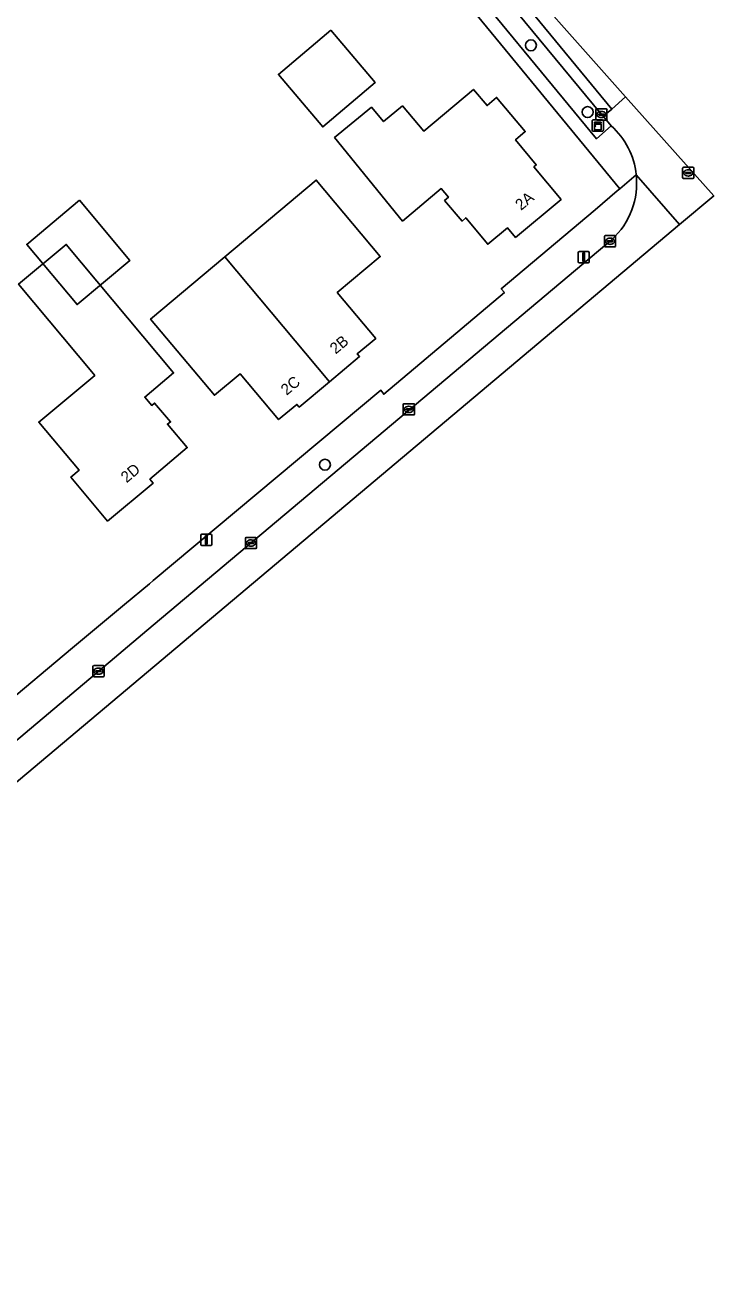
# Model space of a CAD drawing. Extents: x 156702 to 158052, y 387630 to 388992.
# Drawn here: x 157599.6 to 157661.3, y 387864.2 to 387977.5 of the extents above; entities that cross this region are included whole.
import ezdxf

# ---------------------------------------------------------------- set-up
doc = ezdxf.new("R2010")
doc.units = 0
for name, color, linetype in [('IMGEO_Boom', 7, 'Continuous'), ('IMGEO_Erf', 7, 'Continuous'), ('IMGEO_Groenvoorziening', 7, 'Continuous'), ('IMGEO_Kast', 7, 'Continuous'), ('IMGEO_Kolk', 7, 'Continuous'), ('IMGEO_Lichtmast', 7, 'Continuous'), ('IMGEO_Pand', 7, 'Continuous'), ('IMGEO_Pand_nummerreeks', 7, 'Continuous'), ('IMGEO_Pand_vergunning_verleend', 7, 'Continuous'), ('IMGEO_Rijbaan_lokaal_open', 7, 'Continuous'), ('IMGEO_Rioolput', 7, 'Continuous'), ('IMGEO_Voetpad_open', 7, 'Continuous')]:
    doc.layers.add(name, color=color, linetype=linetype)

msp = doc.modelspace()

# ---------------------------------------------------------------- linework, layer by layer
at = {"layer": 'IMGEO_Boom'}
for centre in [(157644.93, 387975.67), (157650.01, 387969.69), (157626.48, 387938.13)]:
    msp.add_circle(centre, 0.489, dxfattribs=at)
at = {"layer": 'IMGEO_Erf'}
for points in [[(157610.76, 387927.47), (157611.11, 387927.75), (157631.49, 387944.79), (157631.75, 387944.44), (157642.56, 387953.55), (157642.27, 387953.88), (157650.67, 387960.94), (157652.64, 387962.64), (157652.9, 387962.82), (157636.22, 387983.07), (157635.31, 387982.52)], [(157590.77, 387910.76), (157603.87, 387921.74), (157608.52, 387925.63), (157610.76, 387927.47)]]:
    msp.add_lwpolyline(points, dxfattribs=at)
for points in [[(157627.34, 387967.41), (157630.65, 387970.13), (157631.73, 387968.85), (157633.42, 387970.25), (157635.33, 387967.99), (157639.78, 387971.72), (157641, 387970.28), (157641.86, 387971.01), (157644.42, 387967.95), (157643.56, 387967.21), (157645.41, 387964.97), (157645.2, 387964.78), (157647.63, 387961.87), (157643.56, 387958.48), (157642.83, 387959.34), (157641.07, 387957.86), (157639.09, 387960.23), (157638.76, 387959.93), (157637.19, 387961.77), (157637.54, 387962.07), (157636.9, 387962.84), (157633.43, 387959.93)], [(157610.86, 387951.17), (157617.51, 387956.73), (157625.71, 387963.6), (157631.43, 387956.76), (157627.59, 387953.54), (157631.03, 387949.43), (157629.37, 387948.06), (157629.59, 387947.82), (157626.89, 387945.55), (157624.18, 387943.28), (157623.97, 387943.52), (157622.33, 387942.17), (157618.9, 387946.26), (157616.59, 387944.34)], [(157599.04, 387954.29), (157603.31, 387957.85), (157612.93, 387946.34), (157610.34, 387944.19), (157610.97, 387943.43), (157611.23, 387943.65), (157612.65, 387941.96), (157612.38, 387941.76), (157614.15, 387939.66), (157610.81, 387936.83), (157611.1, 387936.49), (157607.02, 387933.08), (157603.73, 387937.02), (157604.46, 387937.63), (157600.85, 387941.94), (157605.87, 387946.12), (157605.75, 387946.27)]]:
    msp.add_lwpolyline(points, close=True, dxfattribs=at)
at = {"layer": 'IMGEO_Groenvoorziening'}
msp.add_lwpolyline([(157636.52, 387983.99), (157636.86, 387984.23), (157650.8, 387967.3), (157652.11, 387968.45), (157651.4, 387969.32), (157651.24, 387969.48), (157639.51, 387983.68), (157638.8, 387984.55)], dxfattribs=at)
at = {"layer": 'IMGEO_Kast'}
for p, q in [((157650.42, 387968.06), (157650.42, 387968.9)), ((157650.42, 387968.9), (157650.42, 387968.06)), ((157650.49, 387968.99), (157651.33, 387968.99)), ((157651.33, 387968.99), (157650.49, 387968.99)), ((157651.42, 387968.91), (157651.42, 387968.07)), ((157651.42, 387968.07), (157651.42, 387968.91)), ((157651.34, 387967.99), (157650.5, 387967.99)), ((157650.5, 387967.99), (157651.34, 387967.99))]:
    msp.add_line(p, q, dxfattribs=at)
for points in [[(157650.61, 387968.78), (157651.21, 387968.78), (157651.21, 387968.69), (157650.61, 387968.69), (157650.61, 387968.78)], [(157650.61, 387968.6), (157651.21, 387968.6), (157651.21, 387968.11), (157650.61, 387968.11), (157650.61, 387968.6)]]:
    msp.add_lwpolyline(points, dxfattribs=at)
msp.add_circle((157650.69, 387968.45), 0.0377, dxfattribs=at)
for centre, start, end in [((157650.49, 387968.91), 92.4484, 184.2845), ((157650.49, 387968.91), 92.4484, 184.2845), ((157651.34, 387968.91), 2.4484, 94.2845), ((157651.34, 387968.91), 2.4484, 94.2845), ((157650.49, 387968.06), 182.4484, 274.2845), ((157650.49, 387968.06), 182.4484, 274.2845), ((157651.34, 387968.06), 272.4484, 4.2845), ((157651.34, 387968.06), 272.4484, 4.2845)]:
    msp.add_arc(centre, 0.0779, start, end, dxfattribs=at)
at = {"layer": 'IMGEO_Kolk'}
for p, q in [((157650.74, 387969.05), (157650.74, 387969.9)), ((157650.82, 387969.98), (157651.67, 387969.98)), ((157651.74, 387969.9), (157651.74, 387969.05)), ((157651.67, 387968.98), (157650.82, 387968.98)), ((157651, 387969.47), (157651, 387969.48)), ((157651.04, 387969.52), (157651.44, 387969.52)), ((157651.44, 387969.43), (157651.04, 387969.43)), ((157651.23, 387969.76), (157651.26, 387969.76)), ((157651.25, 387969.2), (157651.23, 387969.2)), ((157651.49, 387969.48), (157651.49, 387969.47)), ((157651.52, 387957.71), (157651.52, 387958.56)), ((157651.59, 387958.64), (157652.44, 387958.64)), ((157652.52, 387958.56), (157652.52, 387957.71)), ((157652.44, 387957.63), (157651.59, 387957.63)), ((157651.78, 387958.13), (157651.78, 387958.14)), ((157651.82, 387958.18), (157652.22, 387958.18)), ((157652.21, 387958.09), (157651.82, 387958.09)), ((157652.03, 387957.86), (157652, 387957.86)), ((157652.01, 387958.41), (157652.03, 387958.41)), ((157652.26, 387958.14), (157652.26, 387958.13)), ((157633.5, 387942.66), (157633.5, 387943.51)), ((157633.57, 387943.58), (157634.42, 387943.58)), ((157633.75, 387943.08), (157633.75, 387943.09)), ((157634.19, 387943.04), (157633.79, 387943.04)), ((157633.8, 387943.13), (157634.2, 387943.13)), ((157633.98, 387943.36), (157634.01, 387943.36)), ((157634.01, 387942.8), (157633.98, 387942.8)), ((157634.24, 387943.09), (157634.24, 387943.08)), ((157634.5, 387943.51), (157634.5, 387942.66)), ((157634.42, 387942.58), (157633.57, 387942.58)), ((157619.36, 387930.69), (157619.36, 387931.54)), ((157619.43, 387931.62), (157620.29, 387931.62)), ((157619.85, 387931.4), (157619.87, 387931.4)), ((157620.36, 387931.54), (157620.36, 387930.69)), ((157620.29, 387930.62), (157619.43, 387930.62)), ((157619.62, 387931.11), (157619.62, 387931.12)), ((157619.66, 387931.16), (157620.06, 387931.16)), ((157620.05, 387931.07), (157619.66, 387931.07)), ((157619.87, 387930.84), (157619.84, 387930.84)), ((157620.1, 387931.12), (157620.1, 387931.11)), ((157605.7, 387919.22), (157605.7, 387920.08)), ((157605.77, 387920.15), (157606.62, 387920.15)), ((157606.7, 387920.08), (157606.7, 387919.22)), ((157606.62, 387919.15), (157605.77, 387919.15)), ((157605.95, 387919.64), (157605.95, 387919.66)), ((157606.39, 387919.61), (157605.99, 387919.61)), ((157606, 387919.69), (157606.39, 387919.69)), ((157606.18, 387919.93), (157606.21, 387919.93)), ((157606.21, 387919.37), (157606.18, 387919.37)), ((157606.44, 387919.66), (157606.44, 387919.64))]:
    msp.add_line(p, q, dxfattribs=at)
for points in [[(157650.74, 387969.05), (157650.74, 387969.9)], [(157650.82, 387969.98), (157651.67, 387969.98)], [(157651.74, 387969.9), (157651.74, 387969.05)], [(157651.67, 387968.98), (157650.82, 387968.98)], [(157651.52, 387957.71), (157651.52, 387958.56)], [(157651.59, 387958.64), (157652.44, 387958.64)], [(157652.52, 387958.56), (157652.52, 387957.71)], [(157652.44, 387957.63), (157651.59, 387957.63)], [(157633.5, 387942.66), (157633.5, 387943.51)], [(157633.57, 387943.58), (157634.42, 387943.58)], [(157634.5, 387943.51), (157634.5, 387942.66)], [(157634.42, 387942.58), (157633.57, 387942.58)], [(157619.36, 387930.69), (157619.36, 387931.54)], [(157619.43, 387931.62), (157620.29, 387931.62)], [(157620.36, 387931.54), (157620.36, 387930.69)], [(157620.29, 387930.62), (157619.43, 387930.62)], [(157605.7, 387919.22), (157605.7, 387920.08)], [(157605.77, 387920.15), (157606.62, 387920.15)], [(157606.7, 387920.08), (157606.7, 387919.22)], [(157606.62, 387919.15), (157605.77, 387919.15)]]:
    msp.add_lwpolyline(points, dxfattribs=at)
for centre, radius, start, end in [((157650.82, 387969.9), 0.0765, 91.552, 178.448), ((157650.82, 387969.9), 0.0765, 91.552, 178.448), ((157651.67, 387969.9), 0.0765, 1.552, 88.448), ((157651.67, 387969.9), 0.0765, 1.552, 88.448), ((157650.82, 387969.05), 0.0765, 181.552, 268.448), ((157650.82, 387969.05), 0.0765, 181.552, 268.448), ((157651.04, 387969.48), 0.0403, 85.8775, 175.7526), ((157651.04, 387969.47), 0.0366, 178.938, 274.7102), ((157651.45, 387969.48), 0.0386, 1.7309, 96.639), ((157651.44, 387969.48), 0.043, 264.8664, 352.4533), ((157651.67, 387969.05), 0.0765, 271.552, 358.448), ((157651.67, 387969.05), 0.0765, 271.552, 358.448), ((157651.59, 387958.56), 0.0765, 91.552, 178.448), ((157651.59, 387958.56), 0.0765, 91.552, 178.448), ((157652.44, 387958.56), 0.0765, 1.552, 88.448), ((157652.44, 387958.56), 0.0765, 1.552, 88.448), ((157651.59, 387957.71), 0.0765, 181.552, 268.448), ((157651.59, 387957.71), 0.0765, 181.552, 268.448), ((157651.82, 387958.14), 0.0403, 85.8775, 175.7526), ((157651.81, 387958.13), 0.0366, 178.938, 274.7102), ((157652.22, 387958.13), 0.043, 264.8664, 352.4533), ((157652.22, 387958.14), 0.0386, 1.7309, 96.639), ((157652.44, 387957.71), 0.0765, 271.552, 358.448), ((157652.44, 387957.71), 0.0765, 271.552, 358.448), ((157633.57, 387943.51), 0.0765, 91.552, 178.448), ((157633.57, 387943.51), 0.0765, 91.552, 178.448), ((157633.57, 387942.66), 0.0765, 181.552, 268.448), ((157633.57, 387942.66), 0.0765, 181.552, 268.448), ((157633.8, 387943.09), 0.0403, 85.8775, 175.7526), ((157633.79, 387943.08), 0.0366, 178.938, 274.7102), ((157634.2, 387943.08), 0.043, 264.8664, 352.4533), ((157634.2, 387943.09), 0.0386, 1.7309, 96.639), ((157634.42, 387943.51), 0.0765, 1.552, 88.448), ((157634.42, 387943.51), 0.0765, 1.552, 88.448), ((157634.42, 387942.66), 0.0765, 271.552, 358.448), ((157634.42, 387942.66), 0.0765, 271.552, 358.448), ((157619.43, 387931.54), 0.0765, 91.552, 178.448), ((157619.43, 387931.54), 0.0765, 91.552, 178.448), ((157620.28, 387931.54), 0.0765, 1.552, 88.448), ((157620.28, 387931.54), 0.0765, 1.552, 88.448), ((157619.43, 387930.69), 0.0765, 181.552, 268.448), ((157619.43, 387930.69), 0.0765, 181.552, 268.448), ((157619.66, 387931.12), 0.0403, 85.8775, 175.7526), ((157619.65, 387931.11), 0.0366, 178.938, 274.7102), ((157620.06, 387931.12), 0.043, 264.8664, 352.4533), ((157620.06, 387931.12), 0.0386, 1.7309, 96.639), ((157620.28, 387930.69), 0.0765, 271.552, 358.448), ((157620.28, 387930.69), 0.0765, 271.552, 358.448), ((157605.77, 387920.07), 0.0765, 91.552, 178.448), ((157605.77, 387920.07), 0.0765, 91.552, 178.448), ((157606.62, 387920.07), 0.0765, 1.552, 88.448), ((157606.62, 387920.07), 0.0765, 1.552, 88.448), ((157605.77, 387919.22), 0.0765, 181.552, 268.448), ((157605.77, 387919.22), 0.0765, 181.552, 268.448), ((157605.99, 387919.65), 0.0403, 85.8775, 175.7526), ((157605.99, 387919.64), 0.0366, 178.938, 274.7102), ((157606.4, 387919.65), 0.0386, 1.7309, 96.639), ((157606.4, 387919.65), 0.043, 264.8664, 352.4533), ((157606.62, 387919.22), 0.0765, 271.552, 358.448), ((157606.62, 387919.22), 0.0765, 271.552, 358.448)]:
    msp.add_arc(centre, radius, start, end, dxfattribs=at)
for centre, major_axis, ratio, start_param, end_param in [((157651.23, 387969.48), (-0.387, 0.002), 0.722429, 4.712389, 7.853982), ((157651.25, 387969.48), (-0.39, 0.002), 0.717154, 1.570796, 4.712389), ((157652, 387958.13), (-0.387, 0.002), 0.722429, 4.712389, 7.853982), ((157652.03, 387958.13), (-0.39, 0.002), 0.717154, 1.570796, 4.712389), ((157633.98, 387943.08), (-0.387, 0.002), 0.722429, 4.712389, 7.853982), ((157634.01, 387943.08), (-0.39, 0.002), 0.717154, 1.570796, 4.712389), ((157619.85, 387931.12), (-0.387, 0.002), 0.722429, 4.712389, 7.853982), ((157619.87, 387931.12), (-0.39, 0.002), 0.717154, 1.570796, 4.712389), ((157606.18, 387919.65), (-0.387, 0.002), 0.722429, 4.712389, 7.853982), ((157606.21, 387919.65), (-0.39, 0.002), 0.717154, 1.570796, 4.712389)]:
    msp.add_ellipse(centre, major_axis=major_axis, ratio=ratio, start_param=start_param, end_param=end_param, dxfattribs=at)
at = {"layer": 'IMGEO_Lichtmast'}
for p, q in [((157649.17, 387956.3), (157649.17, 387957.1)), ((157649.17, 387957.1), (157649.17, 387956.3)), ((157649.27, 387957.2), (157650.06, 387957.2)), ((157650.06, 387957.2), (157649.27, 387957.2)), ((157650.16, 387957.1), (157650.16, 387956.3)), ((157650.16, 387956.3), (157650.16, 387957.1)), ((157650.06, 387956.2), (157649.27, 387956.2)), ((157649.27, 387956.2), (157650.06, 387956.2)), ((157615.36, 387931), (157615.36, 387931.8)), ((157615.36, 387931.8), (157615.36, 387931)), ((157615.46, 387931.9), (157616.25, 387931.9)), ((157616.25, 387931.9), (157615.46, 387931.9)), ((157616.35, 387931.8), (157616.35, 387931)), ((157616.35, 387931), (157616.35, 387931.8)), ((157616.25, 387930.9), (157615.46, 387930.9)), ((157615.46, 387930.9), (157616.25, 387930.9))]:
    msp.add_line(p, q, dxfattribs=at)
for points in [[(157649.59, 387957.08), (157649.74, 387957.08), (157649.74, 387956.33), (157649.59, 387956.33), (157649.59, 387957.08)], [(157615.78, 387931.78), (157615.93, 387931.78), (157615.93, 387931.03), (157615.78, 387931.03), (157615.78, 387931.78)]]:
    msp.add_lwpolyline(points, dxfattribs=at)
for centre, start, end in [((157649.27, 387957.1), 90, 180), ((157649.27, 387957.1), 90, 180), ((157649.27, 387956.3), 180, 270), ((157649.27, 387956.3), 180, 270), ((157650.06, 387957.1), 0, 90), ((157650.06, 387957.1), 360, 90), ((157650.06, 387956.3), 270, 0), ((157650.06, 387956.3), 270, 0), ((157615.46, 387931.8), 90, 180), ((157615.46, 387931.8), 90, 180), ((157616.25, 387931.8), 0, 90), ((157616.25, 387931.8), 360, 90), ((157615.46, 387931), 180, 270), ((157615.46, 387931), 180, 270), ((157616.25, 387931), 270, 0), ((157616.25, 387931), 270, 0)]:
    msp.add_arc(centre, 0.1, start, end, dxfattribs=at)
at = {"layer": 'IMGEO_Pand'}
for points in [[(157641.86, 387971.01), (157641, 387970.28), (157639.78, 387971.72), (157635.33, 387967.99), (157633.42, 387970.25), (157631.73, 387968.85), (157630.65, 387970.13), (157627.34, 387967.41), (157633.43, 387959.93), (157636.9, 387962.84), (157637.54, 387962.07), (157637.19, 387961.77), (157638.76, 387959.93), (157639.09, 387960.23), (157641.07, 387957.86), (157642.83, 387959.34), (157643.56, 387958.48), (157647.63, 387961.87), (157645.2, 387964.78), (157645.41, 387964.97), (157643.56, 387967.21), (157644.42, 387967.95)], [(157625.71, 387963.6), (157617.51, 387956.73), (157626.89, 387945.55), (157629.59, 387947.82), (157629.37, 387948.06), (157631.03, 387949.43), (157627.59, 387953.54), (157631.43, 387956.76)], [(157611.23, 387943.65), (157610.97, 387943.43), (157610.34, 387944.19), (157612.93, 387946.34), (157603.31, 387957.85), (157599.04, 387954.29), (157605.75, 387946.27), (157605.87, 387946.12), (157600.85, 387941.94), (157604.46, 387937.63), (157603.73, 387937.02), (157607.02, 387933.08), (157611.1, 387936.49), (157610.81, 387936.83), (157614.15, 387939.66), (157612.38, 387941.76), (157612.65, 387941.96)], [(157617.51, 387956.73), (157610.86, 387951.17), (157616.59, 387944.34), (157618.9, 387946.26), (157622.33, 387942.17), (157623.97, 387943.52), (157624.18, 387943.28), (157626.89, 387945.55)]]:
    msp.add_lwpolyline(points, close=True, dxfattribs=at)
at = {"layer": 'IMGEO_Pand_vergunning_verleend'}
for points in [[(157627.01, 387977.02), (157630.98, 387972.34), (157626.29, 387968.37), (157622.32, 387973.06)], [(157604.49, 387961.8), (157609.01, 387956.41), (157604.29, 387952.46), (157599.77, 387957.85)]]:
    msp.add_lwpolyline(points, close=True, dxfattribs=at)
at = {"layer": 'IMGEO_Rijbaan_lokaal_open'}
for points in [[(157653.4, 387971.07), (157641.25, 387984.74), (157634.52, 387998.32), (157633.01, 388010.64), (157628.79, 388082.42), (157626.67, 388082.39), (157626.67, 388082.15), (157628.23, 388060.39), (157631.37, 388017.19), (157632.02, 388009.07), (157632.32, 388005.94), (157632.84, 388001.77), (157633.12, 388000), (157633.47, 387997.82), (157634.1, 387995.21), (157634.19, 387994.82)], [(157638.8, 387984.55), (157639.51, 387983.68), (157651.24, 387969.48), (157651.4, 387969.32), (157652.19, 387969.96), (157639.29, 387985.62)], [(157639.29, 387985.62), (157652.19, 387969.96), (157653.4, 387971.07)], [(157658.24, 387959.62), (157661.3, 387962.19), (157653.4, 387971.07), (157652.19, 387969.96), (157651.4, 387969.32), (157652.11, 387968.45)], [(157543.93, 387864.19), (157554.63, 387872.57), (157658.24, 387959.62), (157654.36, 387964.09)], [(157654.36, 387964.09), (157658.24, 387959.62)], [(157652.19, 387958.29), (157652.02, 387958.13), (157650.99, 387957.28), (157610.52, 387923.28), (157605.9, 387919.39), (157595.41, 387910.58), (157592.73, 387908.35), (157587.17, 387903.71), (157587.04, 387903.6), (157580.35, 387898), (157574.13, 387892.79), (157569.5, 387888.91), (157559.18, 387880.27), (157552.71, 387874.85), (157547.96, 387870.88), (157544.4, 387867.89), (157543.34, 387867.03), (157542.28, 387866.17), (157543.93, 387864.19)]]:
    msp.add_lwpolyline(points, dxfattribs=at)
for centre, start, end in [((157647.55, 387963.34), 6.3286, 48.2738), ((157647.54, 387963.34), 312.7047, 6.3327)]:
    msp.add_arc(centre, 6.86, start, end, dxfattribs=at)
at = {"layer": 'IMGEO_Rioolput'}
for p, q in [((157658.52, 387963.82), (157658.52, 387964.68)), ((157658.6, 387964.75), (157659.45, 387964.75)), ((157658.78, 387964.24), (157658.78, 387964.26)), ((157658.82, 387964.29), (157659.22, 387964.29)), ((157659.22, 387964.21), (157658.82, 387964.21)), ((157659.01, 387964.53), (157659.03, 387964.53)), ((157659.26, 387964.26), (157659.26, 387964.24)), ((157659.52, 387964.68), (157659.52, 387963.82)), ((157659.45, 387963.75), (157658.6, 387963.75)), ((157659.03, 387963.97), (157659.01, 387963.97))]:
    msp.add_line(p, q, dxfattribs=at)
for points in [[(157658.52, 387963.82), (157658.52, 387964.68)], [(157658.6, 387964.75), (157659.45, 387964.75)], [(157659.52, 387964.68), (157659.52, 387963.82)], [(157659.45, 387963.75), (157658.6, 387963.75)]]:
    msp.add_lwpolyline(points, dxfattribs=at)
for centre, radius, start, end in [((157658.6, 387964.67), 0.0765, 91.552, 178.448), ((157658.6, 387964.67), 0.0765, 91.552, 178.448), ((157658.82, 387964.25), 0.0403, 85.8775, 175.7526), ((157658.82, 387964.24), 0.0366, 178.938, 274.7102), ((157659.23, 387964.25), 0.0386, 1.7309, 96.639), ((157659.22, 387964.25), 0.043, 264.8664, 352.4533), ((157659.45, 387964.67), 0.0765, 1.552, 88.448), ((157659.45, 387964.67), 0.0765, 1.552, 88.448), ((157658.6, 387963.83), 0.0765, 181.552, 268.448), ((157658.6, 387963.83), 0.0765, 181.552, 268.448), ((157659.45, 387963.83), 0.0765, 271.552, 358.448), ((157659.45, 387963.83), 0.0765, 271.552, 358.448)]:
    msp.add_arc(centre, radius, start, end, dxfattribs=at)
for centre, major_axis, ratio, start_param, end_param in [((157659.01, 387964.25), (-0.387, 0.002), 0.722429, 4.712389, 7.853982), ((157659.03, 387964.25), (-0.39, 0.002), 0.717154, 1.570796, 4.712389)]:
    msp.add_ellipse(centre, major_axis=major_axis, ratio=ratio, start_param=start_param, end_param=end_param, dxfattribs=at)
at = {"layer": 'IMGEO_Voetpad_open'}
for points in [[(157652.11, 387968.45), (157650.8, 387967.3), (157636.86, 387984.23), (157636.52, 387983.99)], [(157635.31, 387982.52), (157636.22, 387983.07), (157652.9, 387962.82), (157654.36, 387964.09)], [(157654.36, 387964.09), (157652.9, 387962.82), (157652.64, 387962.64), (157650.67, 387960.94), (157642.27, 387953.88), (157642.56, 387953.55), (157631.75, 387944.44), (157631.49, 387944.79), (157611.11, 387927.75), (157610.76, 387927.47), (157608.52, 387925.63), (157603.87, 387921.74), (157590.77, 387910.76), (157585.13, 387906.15), (157587.17, 387903.71), (157592.73, 387908.35), (157595.41, 387910.58), (157605.9, 387919.39), (157610.52, 387923.28), (157650.99, 387957.28), (157652.02, 387958.13), (157652.19, 387958.29)]]:
    msp.add_lwpolyline(points, dxfattribs=at)
for centre, start, end in [((157647.55, 387963.34), 6.3286, 48.2738), ((157647.54, 387963.34), 312.7047, 6.3327)]:
    msp.add_arc(centre, 6.86, start, end, dxfattribs=at)

# ---------------------------------------------------------------- texts
at = {"layer": 'IMGEO_Pand_nummerreeks'}
for s, rotation, p in [('2A', 39.557, (157644.04, 387960.84)), ('2B', 39.8378, (157627.44, 387947.98)), ('2C', 39.8378, (157623.05, 387944.29)), ('2D', 39.9695, (157608.72, 387936.46))]:
    msp.add_text(s, height=1, rotation=rotation, dxfattribs=at).set_placement(p)

doc.saveas('drawing.dxf')
